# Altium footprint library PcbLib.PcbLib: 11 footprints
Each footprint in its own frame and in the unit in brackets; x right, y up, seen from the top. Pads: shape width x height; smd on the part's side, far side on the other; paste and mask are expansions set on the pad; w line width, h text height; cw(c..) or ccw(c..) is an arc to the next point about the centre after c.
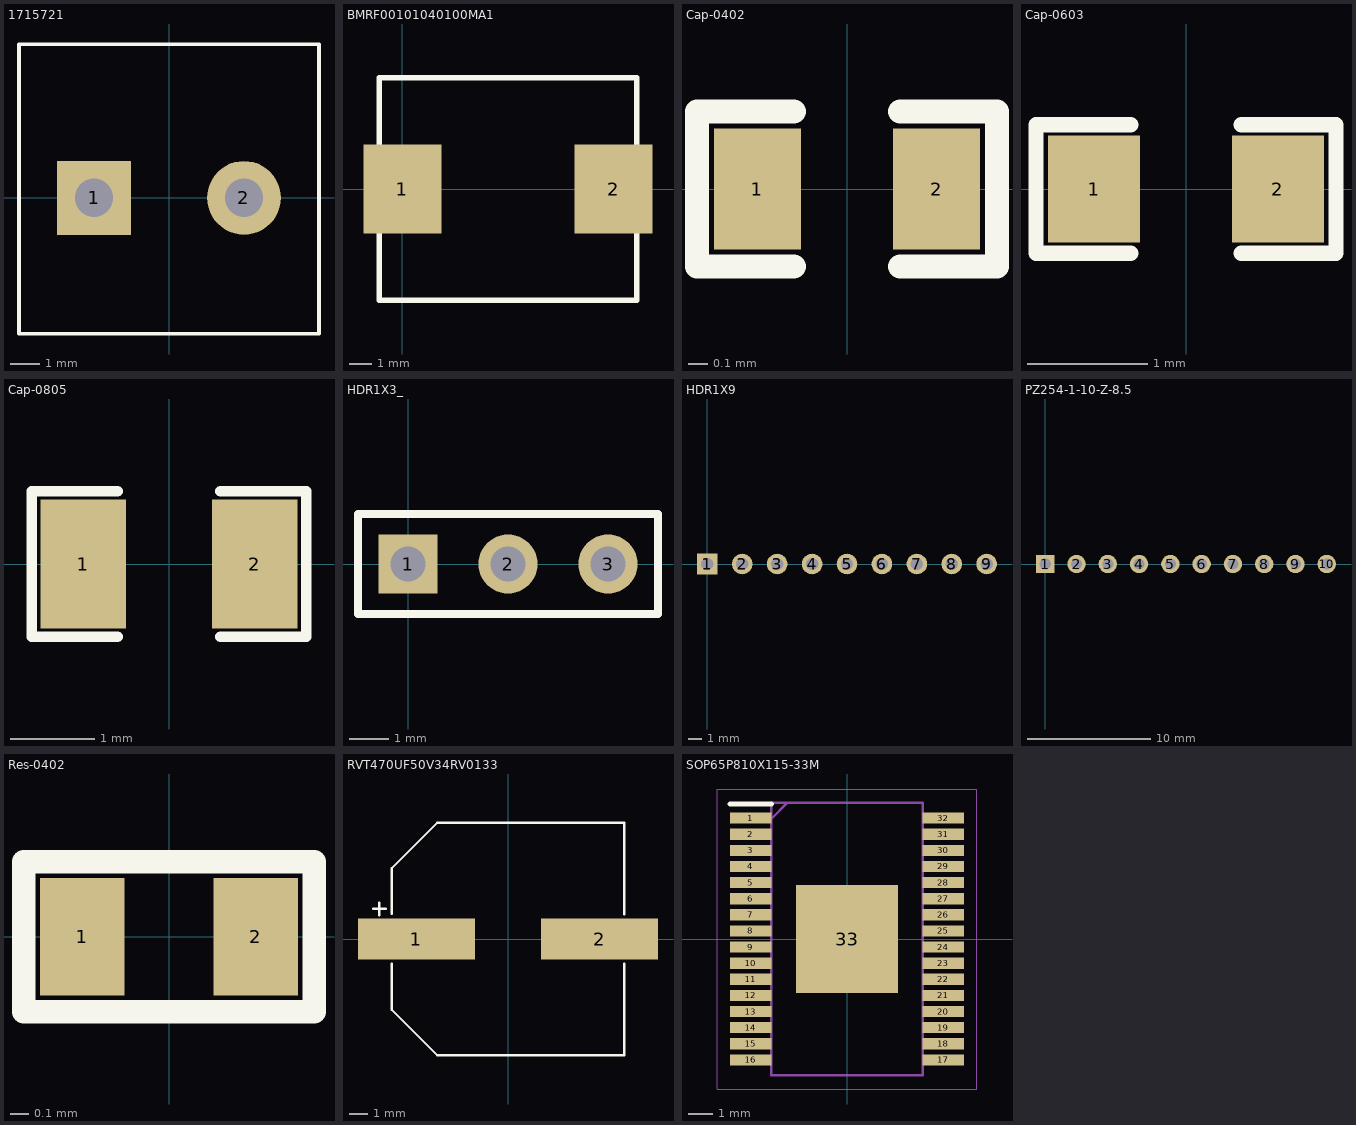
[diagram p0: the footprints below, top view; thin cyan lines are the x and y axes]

## 1715721 [mm]
pads (2):
  rect 2.5x2.5 / inner round 2.5 / far side rect 2.5x2.5 hole 1.3: 1(-2.54,0)
  round 2.5 hole 1.3: 2(2.54,0)
Top Overlay:
  lines w0.127: -5.08,-4.6 5.08,-4.6 5.08,5.2 -5.08,5.2 -5.08,-4.6
3D body "1715721.step": height 14.2, standoff -3.5, extent -5.644,-4.623 5.086,5.207

## BMRF00101040100MA1 [mm]
pads (2):
  rect 3.5x4 smd: 1(0,0) 2(9.5,0)
Top Overlay:
  lines w0.254: -1.05,-5 10.55,-5 10.55,5 -1.05,5 -1.05,-5
3D body: height 4, standoff 0, extent -1.016,-4.953 10.541,4.953

## Cap-0402 [mil]
pads (2):
  rect 18x25 smd mask+2.36: 1(-18.5,0) 2(18.5,0)
Top Overlay:
  lines w5: -11,-16 -31,-16 -31,16 -11,16 ; 11,-16 31,-16 31,16 11,16
3D body "User Library-Capacitor 0402.step": height 18.5, standoff -1.18, extent -19.68,-9.84 19.7,9.85

## Cap-0603 [mil]
pads (2):
  rect 30x35 smd mask+2.36: 1(-30,0) 2(30,0)
Top Overlay:
  lines w5: -18,-21 -49,-21 -49,21 -18,21 ; 18,-21 49,-21 49,21 18,21
3D body "User Library-CAPC1608X09.step": height 34.25, standoff -1.18, extent -31.51,-15.75 31.49,15.74

## Cap-0805 [mil] "SMD 0805"
pads (2):
  rect 40x60 smd mask+2.76: 1(-40,0) 2(40,0)
Top Overlay:
  lines w5: -24,-34 -64,-34 -64,34 -24,34 ; 24,-34 64,-34 64,34 24,34
3D body "User Library-0805 SMD Capacitor.step": height 30, standoff -0.79, extent -39.36,-24.6 39.38,24.61

## HDR1X3_ [mm] "Connector; Header; 3 Position"
pads (3):
  rect 1.5x1.5 hole 0.9: 1(0,0)
  round 1.5 hole 0.9: 2(2.54,0) 3(5.08,0)
Top Overlay:
  lines w0.2: -1.27,-1.27 -1.27,1.27 6.35,1.27 6.35,-1.27 -1.27,-1.27
3D body "User Library-Header_Male_3Pin.STEP": height 8.54, standoff -3, extent -1.27,-1.245 6.35,1.245

## HDR1X9 [mm]
pads (9):
  rect 1.5x1.5 hole 0.9: 1(0,0)
  round 1.5 hole 0.9: 2(2.54,0) 3(5.08,0) 4(7.62,0) 5(10.16,0) 6(12.7,0) 7(15.24,0) 8(17.78,0) 9(20.32,0)
3D body "1x9.STEP": height 8.34, standoff -3, extent -1.27,-1.295 21.59,1.245

## PZ254-1-10-Z-8.5 [mm]
pads (10):
  rect 1.5x1.5 hole 0.9: 1(0,0)
  round 1.5 hole 0.9: 2(2.54,0) 3(5.08,0) 4(7.62,0) 5(10.16,0) 6(12.7,0) 7(15.24,0) 8(17.78,0) 9(20.32,0) 10(22.86,0)
3D body "1X10_Header.step": height 9.51, standoff -3.19, extent -1.27,-1.25 24.13,1.25

## Res-0402 [mil]
pads (2):
  rect 18x25 smd mask+2.17: 1(-18.5,0) 2(18.5,0)
Top Overlay:
  lines w0.13: -32,-17 32,-17
  lines w5: -31,-16 31,-16 31,16 -31,16 -31,-16
3D body "User Library-RES_1005-0402.step": height 16.14, standoff 0, extent -22.63,-10.82 22.64,10.83

## RVT470UF50V34RV0133 [mm]
pads (2):
  rect 6.5x2.3 smd paste+0 mask+0.051: 1(-5.1,0) 2(5.1,0)
Top Overlay:
  lines w0.127: -7.518,1.676 -6.807,1.676 ; -7.163,1.321 -7.163,2.032 ; -6.477,-1.381 -6.477,-3.937 -3.937,-6.477 6.477,-6.477 6.477,-1.381 ; -6.477,1.397 -6.477,3.937 -3.937,6.477 6.477,6.477 6.477,1.381
3D body "C2837182.step": height 13.5, standoff 0, extent -7,-6.5 7,6.501

## SOP65P810X115-33M [mm]
pads (33):
  rect 1.675x0.45 smd: 1(-3.888,4.875) 2(-3.888,4.225) 3(-3.888,3.575) 4(-3.888,2.925) 5(-3.888,2.275) 6(-3.888,1.625) 7(-3.888,0.975) 8(-3.888,0.325) 9(-3.888,-0.325) 10(-3.888,-0.975) 11(-3.888,-1.625) 12(-3.888,-2.275) 13(-3.888,-2.925) 14(-3.888,-3.575) 15(-3.888,-4.225) 16(-3.888,-4.875) 17(3.888,-4.875) 18(3.888,-4.225) 19(3.888,-3.575) 20(3.888,-2.925) 21(3.888,-2.275) 22(3.888,-1.625) 23(3.888,-0.975) 24(3.888,-0.325) 25(3.888,0.325) 26(3.888,0.975) 27(3.888,1.625) 28(3.888,2.275) 29(3.888,2.925) 30(3.888,3.575) 31(3.888,4.225) 32(3.888,4.875)
  rect 4.11x4.36 smd: 33(0,0)
Top Overlay:
  lines w0.2: -4.725,5.45 -3.05,5.45
Mechanical 15:
  lines w0.1: -3.05,4.85 -2.4,5.5 ; -3.05,-5.5 -3.05,5.5 3.05,5.5 3.05,-5.5 -3.05,-5.5
Mechanical 20:
  lines w0.05: -5.225,-6.05 -5.225,6.05 5.225,6.05 5.225,-6.05 -5.225,-6.05
3D body "TAS5828MDADR.stp": height 1.15, standoff 0, extent -4.05,-5.5 4.05,5.5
